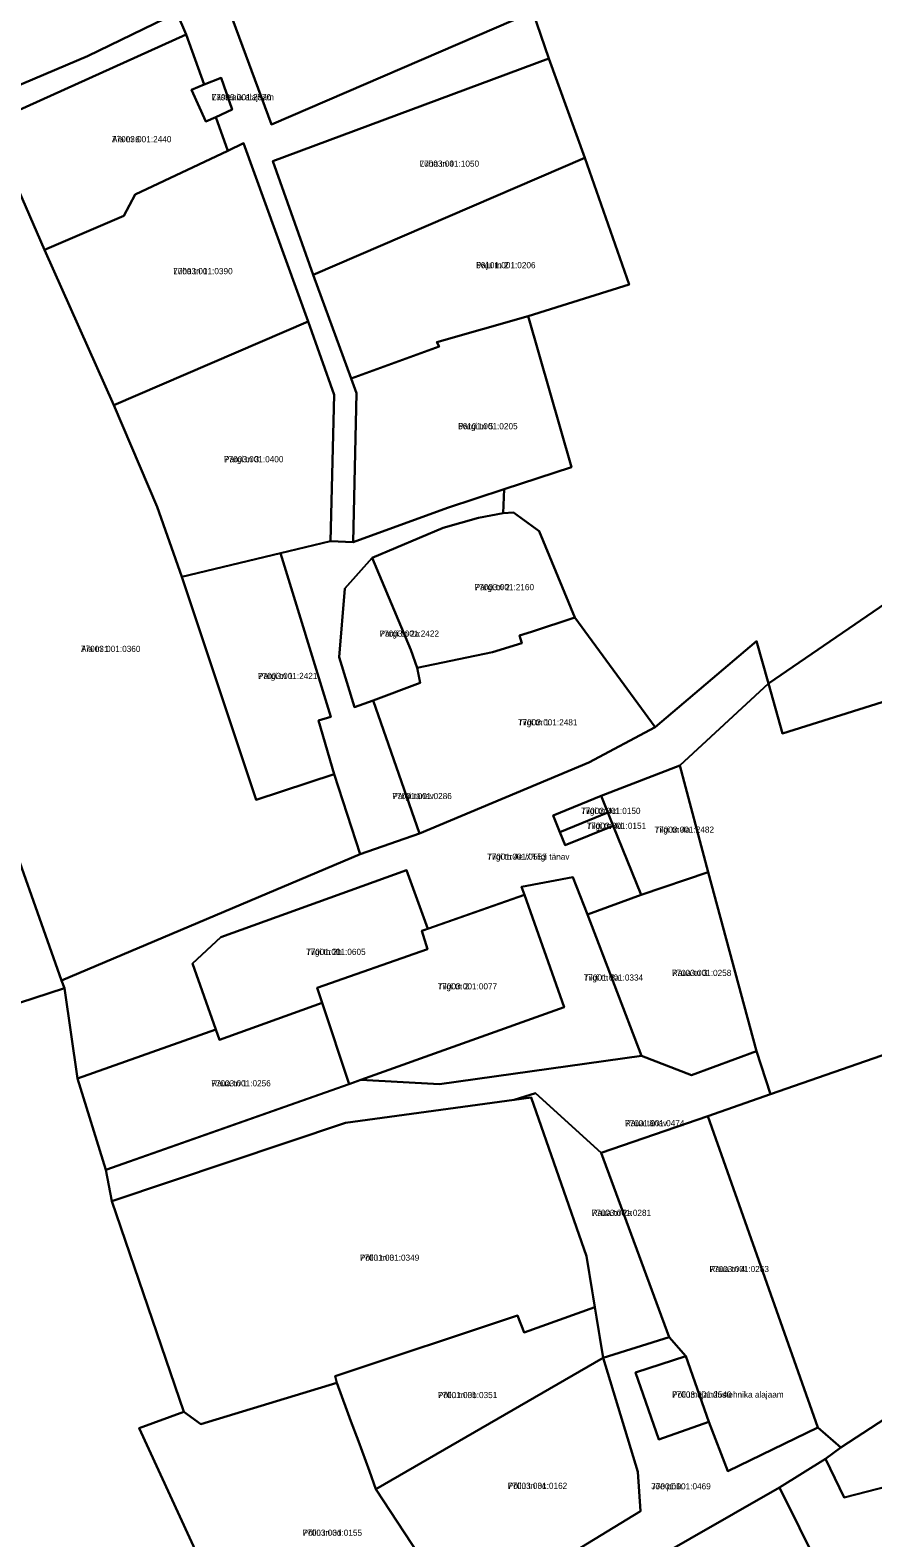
# Model space of a CAD drawing. Extents: x 623860 to 651189, y 6568632 to 6595301.
# Drawn here: x 638458.9 to 638664.4, y 6582592.3 to 6582960 of the extents above; entities that cross this region are included whole.
import ezdxf

# ---------------------------------------------------------------- set-up
doc = ezdxf.new("R2010")
doc.units = 0
for name, color, linetype in [('L_AADRESS', 7, 'Continuous'), ('PIIR', 7, 'Continuous'), ('TUNNUS', 7, 'Continuous')]:
    doc.layers.add(name, color=color, linetype=linetype)

msp = doc.modelspace()

# ---------------------------------------------------------------- linework, layer by layer
at = {"layer": 'PIIR'}
for points in [[(638441.95, 6582960.39), (638449.18, 6582943.68), (638472.86, 6582953.63), (638494.66, 6582964.27), (638496.97, 6582958.94), (638449.36, 6582937.5), (638455.18, 6582923.08), (638403.16, 6582902.43), (638397.95, 6582911.66), (638392.51, 6582924.55), (638435.51, 6582943.45), (638413.71, 6582995.3)], [(638507.42, 6582964.88), (638517.72, 6582937.01), (638581.48, 6582964.47), (638585.43, 6582953.12), (638518.12, 6582928.09), (638527.91, 6582900.31), (638537.16, 6582875.03), (638538.46, 6582871.46), (638537.64, 6582835.1), (638532.13, 6582835.38), (638533.02, 6582871.07), (638526.72, 6582888.93), (638510.96, 6582932.43), (638507.14, 6582930.54), (638504.18, 6582938.79), (638508.16, 6582940.7), (638505.46, 6582948.4), (638501.34, 6582946.74), (638496.97, 6582958.94), (638494.66, 6582964.27)], [(638700.6, 6582842.87), (638638.96, 6582800.63), (638636.04, 6582811.01), (638611.37, 6582790.01), (638591.72, 6582816.77), (638583, 6582837.8), (638576.82, 6582842.37), (638574.23, 6582842.24), (638574.51, 6582848.03), (638590.96, 6582853.43), (638580.35, 6582890.23), (638605.01, 6582897.96), (638594.15, 6582928.86), (638585.43, 6582953.12), (638581.48, 6582964.47)], [(638445.49, 6582570.97), (638426.9, 6582622.64), (638423.42, 6582621.38), (638411.89, 6582653.77), (638425.49, 6582660.29), (638421.83, 6582683.41), (638420.27, 6582685.16), (638418.11, 6582685.47), (638434.03, 6582715.51), (638467.23, 6582726.36), (638470.4, 6582704.35), (638477.32, 6582682.07), (638478.85, 6582674.37), (638496.41, 6582623.01), (638485.5, 6582619.07), (638515.25, 6582554.41)]]:
    msp.add_lwpolyline(points, dxfattribs=at)
for points in [[(638581.48, 6582964.47), (638517.72, 6582937.01), (638507.42, 6582964.88), (638572.63, 6582989.51), (638580.42, 6582967.62)], [(638488.61, 6582979.45), (638494.66, 6582964.27), (638472.86, 6582953.63), (638449.18, 6582943.68), (638441.95, 6582960.39)], [(638496.97, 6582958.94), (638501.34, 6582946.74), (638498.21, 6582945.47), (638501.72, 6582937.7), (638504.18, 6582938.79), (638507.14, 6582930.54), (638484.52, 6582919.91), (638481.76, 6582914.74), (638462.39, 6582906.4), (638455.18, 6582923.08), (638449.36, 6582937.5)], [(638527.91, 6582900.31), (638518.12, 6582928.09), (638585.43, 6582953.12), (638594.15, 6582928.86)], [(638505.46, 6582948.4), (638508.16, 6582940.7), (638504.18, 6582938.79), (638501.72, 6582937.7), (638498.21, 6582945.47), (638501.34, 6582946.74)], [(638481.76, 6582914.74), (638484.52, 6582919.91), (638507.14, 6582930.54), (638510.96, 6582932.43), (638526.72, 6582888.93), (638479.31, 6582868.54), (638462.39, 6582906.4)], [(638537.16, 6582875.03), (638527.91, 6582900.31), (638594.15, 6582928.86), (638605.01, 6582897.96), (638580.35, 6582890.23), (638558.12, 6582883.92), (638558.61, 6582882.88)], [(638437.55, 6582810.55), (638443.26, 6582812.5), (638403.16, 6582902.43), (638455.18, 6582923.08), (638462.39, 6582906.4), (638479.31, 6582868.54), (638489.9, 6582843.74), (638495.87, 6582826.67), (638514.05, 6582772.26), (638533.04, 6582778.51), (638539.42, 6582759.02), (638466.54, 6582728.22), (638450.47, 6582773.62)], [(638538.46, 6582871.46), (638537.16, 6582875.03), (638558.61, 6582882.88), (638558.12, 6582883.92), (638580.35, 6582890.23), (638590.96, 6582853.43), (638574.51, 6582848.03), (638560.66, 6582843.49), (638537.64, 6582835.1)], [(638489.9, 6582843.74), (638479.31, 6582868.54), (638526.72, 6582888.93), (638533.02, 6582871.07), (638532.13, 6582835.38), (638519.98, 6582832.46), (638495.87, 6582826.67)], [(638519.98, 6582832.46), (638532.13, 6582835.38), (638537.64, 6582835.1), (638560.66, 6582843.49), (638574.51, 6582848.03), (638574.23, 6582842.24), (638568.24, 6582841.06), (638559.59, 6582838.65), (638542.33, 6582831.28), (638535.61, 6582823.81), (638534.24, 6582807.07), (638537.98, 6582794.87), (638542.58, 6582796.55), (638553.88, 6582764.11), (638539.42, 6582759.02), (638533.04, 6582778.51), (638529.21, 6582791.62), (638532.23, 6582792.57)], [(638559.59, 6582838.65), (638568.24, 6582841.06), (638574.23, 6582842.24), (638576.82, 6582842.37), (638583, 6582837.8), (638591.72, 6582816.77), (638581.18, 6582813.29), (638578.22, 6582812.33), (638578.8, 6582810.51), (638571.65, 6582808.29), (638553.28, 6582804.47), (638551.73, 6582808.87), (638542.33, 6582831.28)], [(638642.35, 6582788.45), (638638.96, 6582800.63), (638700.6, 6582842.87), (638710.96, 6582809.98)], [(638519.98, 6582832.46), (638532.23, 6582792.57), (638529.21, 6582791.62), (638533.04, 6582778.51), (638514.05, 6582772.26), (638495.87, 6582826.67)], [(638534.24, 6582807.07), (638535.61, 6582823.81), (638542.33, 6582831.28), (638551.73, 6582808.87), (638553.28, 6582804.47), (638553.98, 6582800.84), (638542.58, 6582796.55), (638537.98, 6582794.87)], [(638553.88, 6582764.11), (638542.58, 6582796.55), (638553.98, 6582800.84), (638553.28, 6582804.47), (638571.65, 6582808.29), (638578.8, 6582810.51), (638578.22, 6582812.33), (638581.18, 6582813.29), (638591.72, 6582816.77), (638611.37, 6582790.01), (638595.18, 6582781.43)], [(638617.31, 6582780.7), (638638.96, 6582800.63), (638642.35, 6582788.45), (638710.96, 6582809.98), (638729.23, 6582815.68), (638740.68, 6582780.82), (638740.12, 6582766.01), (638765.57, 6582688), (638729.11, 6582675.07), (638726.9, 6582672.29), (638708.55, 6582724.43), (638685.84, 6582716.61), (638639.45, 6582700.48), (638636.04, 6582710.98), (638624.23, 6582754.66)], [(638466.54, 6582728.22), (638539.42, 6582759.02), (638553.88, 6582764.11), (638595.18, 6582781.43), (638611.37, 6582790.01), (638636.04, 6582811.01), (638638.96, 6582800.63), (638617.31, 6582780.7), (638598.15, 6582773.28), (638586.48, 6582768.43), (638588.06, 6582764.41), (638589.4, 6582761.25), (638601.11, 6582765.96), (638607.93, 6582749.11), (638594.79, 6582744.33), (638591.27, 6582753.42), (638578.76, 6582751.08), (638579.43, 6582749.16), (638555.88, 6582740.84), (638550.72, 6582755.12), (638505.41, 6582738.78), (638498.49, 6582732.41), (638504.2, 6582716.28), (638470.4, 6582704.35), (638467.23, 6582726.36)], [(638607.93, 6582749.11), (638601.11, 6582765.96), (638599.82, 6582769.16), (638598.15, 6582773.28), (638617.31, 6582780.7), (638624.23, 6582754.66)], [(638414.71, 6582756.97), (638450.47, 6582773.62), (638466.54, 6582728.22), (638467.23, 6582726.36), (638434.03, 6582715.51)], [(638586.48, 6582768.43), (638598.15, 6582773.28), (638599.82, 6582769.16), (638593.44, 6582766.59), (638588.06, 6582764.41)], [(638588.06, 6582764.41), (638593.44, 6582766.59), (638599.82, 6582769.16), (638601.11, 6582765.96), (638589.4, 6582761.25)], [(638505.41, 6582738.78), (638550.72, 6582755.12), (638555.88, 6582740.84), (638554.41, 6582740.32), (638555.77, 6582735.89), (638528.87, 6582726.4), (638530.09, 6582722.75), (638505.04, 6582713.79), (638504.2, 6582716.28), (638498.49, 6582732.41)], [(638594.79, 6582744.33), (638607.93, 6582749.11), (638624.23, 6582754.66), (638636.04, 6582710.98), (638620.22, 6582705.15), (638608.01, 6582709.83)], [(638578.76, 6582751.08), (638591.27, 6582753.42), (638594.79, 6582744.33), (638608.01, 6582709.83), (638558.72, 6582702.97), (638539.58, 6582703.98), (638589.12, 6582721.71), (638579.43, 6582749.16)], [(638579.43, 6582749.16), (638589.12, 6582721.71), (638539.58, 6582703.98), (638536.69, 6582702.95), (638530.09, 6582722.75), (638528.87, 6582726.4), (638555.77, 6582735.89), (638554.41, 6582740.32)], [(638470.4, 6582704.35), (638504.2, 6582716.28), (638505.04, 6582713.79), (638530.09, 6582722.75), (638536.69, 6582702.95), (638477.32, 6582682.07)], [(638624.16, 6582695.16), (638639.45, 6582700.48), (638685.84, 6582716.61), (638710.95, 6582654.61), (638700.37, 6582643.44), (638687.41, 6582634.41), (638656.62, 6582614.33), (638651.01, 6582619.22)], [(638477.32, 6582682.07), (638536.6, 6582702.95), (638539.58, 6582703.98), (638558.72, 6582702.97), (638608.01, 6582709.83), (638620.22, 6582705.15), (638636.04, 6582710.98), (638639.45, 6582700.48), (638624.16, 6582695.16), (638598.13, 6582686.18), (638582.15, 6582700.71), (638576.93, 6582699.15), (638535.8, 6582693.54), (638478.85, 6582674.37)], [(638496.41, 6582623.01), (638478.85, 6582674.37), (638535.8, 6582693.54), (638576.93, 6582699.15), (638581.08, 6582699.71), (638594.61, 6582660.98), (638596.63, 6582648.57), (638579.36, 6582642.38), (638577.75, 6582646.54), (638533.27, 6582631.72), (638533.65, 6582630.13), (638500.51, 6582620.05)], [(638576.93, 6582699.15), (638582.15, 6582700.71), (638598.13, 6582686.18), (638614.76, 6582641.26), (638598.63, 6582636.22), (638594.61, 6582660.98), (638581.08, 6582699.71)], [(638598.13, 6582686.18), (638624.16, 6582695.16), (638651.01, 6582619.22), (638629.03, 6582608.58), (638624.42, 6582620.61), (638618.81, 6582636.63), (638614.76, 6582641.26)], [(638536.17, 6582623.4), (638533.65, 6582630.13), (638533.27, 6582631.72), (638577.75, 6582646.54), (638579.36, 6582642.38), (638596.63, 6582648.57), (638598.63, 6582636.22), (638543.23, 6582604.16), (638541.63, 6582608.57), (638538.94, 6582615.88), (638537.11, 6582620.73)], [(638598.63, 6582636.22), (638614.76, 6582641.26), (638618.81, 6582636.63), (638606.55, 6582632.6), (638612.24, 6582616.31), (638624.42, 6582620.61), (638629.03, 6582608.58), (638651.01, 6582619.22), (638656.62, 6582614.33), (638652.89, 6582611.6), (638641.62, 6582604.53), (638608.6, 6582585.61), (638586.17, 6582574.9), (638570.87, 6582571.76), (638584.25, 6582538.39), (638577.55, 6582535.95), (638565.17, 6582570.67), (638564.16, 6582572.25), (638607.76, 6582598.81), (638607.14, 6582608.36)], [(638543.23, 6582604.16), (638598.63, 6582636.22), (638607.14, 6582608.36), (638607.76, 6582598.81), (638564.16, 6582572.25)], [(638618.81, 6582636.63), (638624.4, 6582620.62), (638612.24, 6582616.31), (638606.55, 6582632.6)], [(638693.48, 6582611.4), (638657.41, 6582602.16), (638652.89, 6582611.6), (638656.62, 6582614.33), (638687.41, 6582634.41)], [(638485.5, 6582619.07), (638496.41, 6582623.01), (638500.51, 6582620.05), (638533.65, 6582630.13), (638536.17, 6582623.4), (638537.11, 6582620.73), (638538.94, 6582615.88), (638541.63, 6582608.57), (638543.23, 6582604.16), (638564.16, 6582572.25), (638565.17, 6582570.67), (638555.96, 6582568.82), (638515.25, 6582554.41)], [(638641.62, 6582604.53), (638652.89, 6582611.6), (638657.41, 6582602.16), (638693.48, 6582611.4), (638704.17, 6582580.09), (638661.19, 6582565.2)], [(638641.62, 6582604.53), (638661.19, 6582565.2), (638621.86, 6582551.03), (638608.6, 6582585.61)]]:
    msp.add_lwpolyline(points, close=True, dxfattribs=at)

# ---------------------------------------------------------------- texts
at = {"layer": 'L_AADRESS'}
for s, p in [('Lasteaia alajaam', (638503.18, 6582942.92)), ('Aia tn 6', (638478.84, 6582932.67)), ('Luha tn 4', (638553.89, 6582926.71)), ('Luha tn 1', (638493.78, 6582900.49)), ('Paju tn 2', (638567.66, 6582901.95)), ('Pargi tn 5', (638563.28, 6582862.67)), ('Pargi tn 3', (638506.17, 6582854.62)), ('Pargi tn 2', (638567.29, 6582823.42)), ('Pargi tn 2a', (638544.11, 6582812.08)), ('Aia tn 1', (638471.29, 6582808.36)), ('Pargi tn 1', (638514.45, 6582801.76)), ('Tiigi tn 1', (638577.88, 6582790.44)), ('Pargi tänav', (638547.24, 6582772.47)), ('Tiigi tn 4c', (638593.26, 6582768.85)), ('Tiigi tn 4d', (638594.63, 6582765.21)), ('Tiigi tn 4a', (638611.19, 6582764.27)), ('Tiigi tn 4e // Tiigi tänav', (638570.36, 6582757.68)), ('Tiigi tn 2b', (638526.21, 6582734.46)), ('Tiigi tn 2a', (638593.9, 6582728.2)), ('Raua tn 3', (638615.41, 6582729.33)), ('Tiigi tn 2', (638558.29, 6582726.05)), ('Raua tn 1', (638503.08, 6582702.41)), ('Raua tänav', (638603.97, 6582692.68)), ('Raua tn 2a', (638595.84, 6582670.82)), ('Põllu tn 3', (638539.3, 6582659.88)), ('Raua tn 4', (638624.57, 6582657.11)), ('Põllu tn 3b', (638558.33, 6582626.37)), ('Põllumajandustehnika alajaam', (638615.47, 6582626.5)), ('Põllu tn 3c', (638575.38, 6582604.24)), ('Jõe põik', (638610.39, 6582604.12)), ('Põllu tn 3d', (638525.34, 6582592.79))]:
    msp.add_text(s, height=1.5, dxfattribs=at).set_placement(p)
at = {"layer": 'TUNNUS'}
for s, p in [('77003:001:2570', (638503.18, 6582942.92)), ('77003:001:2440', (638478.84, 6582932.67)), ('77003:001:1050', (638553.89, 6582926.71)), ('77003:001:0390', (638493.78, 6582900.49)), ('66101:001:0206', (638567.66, 6582901.95)), ('66101:001:0205', (638563.28, 6582862.67)), ('77003:001:0400', (638506.17, 6582854.62)), ('77003:001:2160', (638567.29, 6582823.42)), ('77003:001:2422', (638544.11, 6582812.08)), ('77003:001:0360', (638471.29, 6582808.36)), ('77003:001:2421', (638514.45, 6582801.76)), ('77003:001:2481', (638577.88, 6582790.44)), ('77001:001:0286', (638547.24, 6582772.47)), ('77003:001:0150', (638593.26, 6582768.85)), ('77003:001:0151', (638594.63, 6582765.21)), ('77003:001:2482', (638611.19, 6582764.27)), ('77001:001:0553', (638570.36, 6582757.68)), ('77001:001:0605', (638526.21, 6582734.46)), ('77001:001:0334', (638593.9, 6582728.2)), ('77003:001:0258', (638615.41, 6582729.33)), ('77003:001:0077', (638558.29, 6582726.05)), ('77003:001:0256', (638503.08, 6582702.41)), ('77001:001:0474', (638603.97, 6582692.68)), ('77003:001:0281', (638595.84, 6582670.82)), ('77001:001:0349', (638539.3, 6582659.88)), ('77003:001:0263', (638624.57, 6582657.11)), ('77001:001:0351', (638558.33, 6582626.37)), ('77003:001:2540', (638615.47, 6582626.5)), ('77003:001:0162', (638575.38, 6582604.24)), ('77001:001:0469', (638610.39, 6582604.12)), ('77003:001:0155', (638525.34, 6582592.79))]:
    msp.add_text(s, height=1.5, dxfattribs=at).set_placement(p)

doc.saveas('drawing.dxf')
